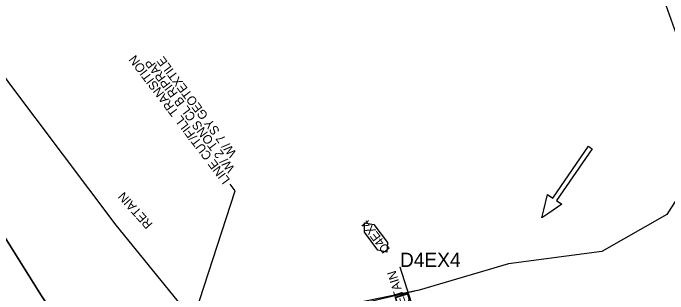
# Model space of a CAD drawing. Extents: x 465700 to 483515, y 488970 to 507540.
# Drawn here: x 476301 to 476667, y 501004.5 to 501161.6 of the extents above; entities that cross this region are included whole.
import ezdxf

# ---------------------------------------------------------------- set-up
doc = ezdxf.new("R2010")
doc.units = 0
for name, color, linetype in [('Default', 7, 'Continuous'), ('Exist Plan Preparation Drainage Flow Arrows', 7, 'Continuous'), ('Exist Plan Preparation Watershed Blue', 7, 'Continuous'), ('Prop Drainage Structure Box Number Symbol CELL', 7, 'Continuous'), ('Prop Drainage Structure Pipe Collar Label', 7, 'Continuous'), ('Prop Drainage Structure Pipe Stub Out CELL', 7, 'Continuous'), ('Prop Erosion Rip Rap Pad at Outlet Label', 7, 'Continuous'), ('Scratch_Level_8', 7, 'Continuous')]:
    doc.layers.add(name, color=color, linetype=linetype)

# ---------------------------------------------------------------- blocks, each defined once
blk = doc.blocks.new('Existing ground flow arrow')
at = {"layer": 'Default'}
blk.add_line((2.5, -4.33), (2.5, -4.33), dxfattribs=at)
blk.add_lwpolyline([(-1.29, -47.2), (-1.28, -12.53), (-4.77, -12.53), (-1.65, -4.33), (0, 0), (1.65, -4.33), (4.78, -12.53), (1.28, -12.52), (1.29, -47.19), (0, -47.2)], close=True, dxfattribs=at)

msp = doc.modelspace()

# ---------------------------------------------------------------- linework, layer by layer
at = {"layer": 'Exist Plan Preparation Watershed Blue'}
for points in [[(476921.2, 501693.96), (476873.97, 501665.49), (476797.54, 501630.58), (476778.04, 501586.57), (476684.08, 501524.02), (476617.13, 501430.2), (476608.09, 501344.67), (476632.2, 501297.34), (476652.85, 501202.84), (476684.48, 501113.94), (476686.07, 501079.86), (476666.3, 501048.93), (476630.01, 501028.21), (476577.87, 501021.26), (476528.03, 501006.59), (476466.6, 500992.22), (476420.26, 500966.99), (476486.96, 500889.51), (476555.03, 500816.27), (476625.62, 500745.44), (476698.65, 500677.13), (476726.48, 500652.21), (476834.31, 500555.52), (476965.29, 500641)], [(476922.43, 500477.32), (476847.82, 500543.91), (476773.22, 500610.51), (476698.65, 500677.13), (476625.62, 500745.44), (476555.03, 500816.27), (476486.96, 500889.51), (476420.26, 500966.99), (476358.7, 501042.92), (476298.67, 501122.89), (476241.47, 501204.91)], [(476965.29, 500641), (476834.31, 500555.52), (476726.48, 500652.21), (476625.62, 500745.44), (476555.03, 500816.27), (476486.96, 500889.51), (476420.26, 500966.99), (476358.7, 501042.92), (476298.67, 501122.89), (476241.47, 501204.91)], [(476652.85, 501202.84), (476684.48, 501113.94), (476686.07, 501079.86), (476666.3, 501048.93), (476630.01, 501028.21), (476577.87, 501021.26), (476528.03, 501006.59), (476497.08, 501000.21), (476482.89, 500996.49), (476466.6, 500992.22), (476455.71, 500986.82), (476443.7, 500979.93), (476439.14, 500977.28), (476420.26, 500966.99), (476358.7, 501042.92), (476298.67, 501122.89), (476241.47, 501204.91)], [(476209, 500683.6), (476345.39, 500652.36), (476467.07, 500616.53), (476565.07, 500627.06), (476600.68, 500664.31), (476574.27, 500687.93), (476537.67, 500723.12), (476510.19, 500751.77), (476483.11, 500782.17), (476453.04, 500818.7), (476434.2, 500842.61), (476385.69, 500904.17), (476387.26, 500905.41), (476372.86, 500924.02), (476358.8, 500942.89), (476340.03, 500969.19), (476316.98, 501003.43), (476294.62, 501039.29)], [(476294.62, 501039.29), (476316.98, 501003.43), (476340.03, 500969.19), (476358.8, 500942.89), (476372.86, 500924.02), (476387.26, 500905.42), (476401.7, 500887.09), (476416.14, 500868.76), (476414.56, 500867.51), (476424.17, 500855.35), (476438.61, 500837.03), (476453.04, 500818.7), (476467.88, 500800.28), (476483.11, 500782.17), (476510.19, 500751.77), (476537.67, 500723.12), (476574.27, 500687.93)]]:
    msp.add_lwpolyline(points, dxfattribs=at)
at = {"layer": 'Prop Drainage Structure Box Number Symbol CELL'}
msp.add_lwpolyline([(476504.93, 501029.08), (476497.32, 501039.13), (476497.42, 501044.35), (476502.66, 501043.37), (476510.27, 501033.32), (476509.83, 501027.97), (476504.93, 501029.08)], dxfattribs=at)
at = {"layer": 'Prop Drainage Structure Pipe Stub Out CELL'}
msp.add_line((476517.23, 501019.61), (476517.23, 501019.61), dxfattribs=at)
msp.add_line((476517.23, 501019.61), (476517.23, 501019.61), dxfattribs=at)
msp.add_lwpolyline([(476517.22, 501019.62), (476517.24, 501019.61), (476517.23, 501019.59), (476517.21, 501019.6), (476517.22, 501019.62)], dxfattribs=at)
at = {"layer": 'Prop Erosion Rip Rap Pad at Outlet Label'}
msp.add_lwpolyline([(476390.32, 500954.98), (476425.16, 501062.12), (476422.28, 501065.93)], dxfattribs=at)
at = {"layer": 'Scratch_Level_8'}
msp.add_line((476517.23, 501019.61), (476525.77, 500992.62), dxfattribs=at)

# ---------------------------------------------------------------- block references
at = {"layer": 'Exist Plan Preparation Drainage Flow Arrows', "xscale": 1.012407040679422, "yscale": 1.0124070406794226, "rotation": 145.49469097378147}
msp.add_blockref('Existing ground flow arrow', (476596.51, 501047), dxfattribs=at)

# ---------------------------------------------------------------- texts
at = {"layer": 'Prop Drainage Structure Box Number Symbol CELL'}
msp.add_text('D4EX4', height=5, rotation=127.1208, dxfattribs=at).set_placement((476511.92, 501029.61))
at = {"layer": 'Prop Drainage Structure Pipe Collar Label'}
for rotation, p in [(131.746, (476379.32, 501043.7)), (107.5926, (476522.15, 500994.59))]:
    msp.add_text('RETAIN', height=5, rotation=rotation, dxfattribs=at).set_placement(p)
at = {"layer": 'Prop Drainage Structure Pipe Stub Out CELL'}
msp.add_text('SO', height=0.0104, rotation=277.6891, dxfattribs=at).set_placement((476517.22, 501019.61))
at = {"layer": 'Prop Erosion Rip Rap Pad at Outlet Label'}
for s, p in [('LINE CUT/FILL TRANSITION ', (476422.48, 501068.37)), ('W/ 2 TONS CL B RIPRAP', (476425.18, 501074.74)), ('W/ 7 SY GEOTEXTILE', (476426.22, 501083.32))]:
    msp.add_text(s, height=5, rotation=127.1092, dxfattribs=at).set_placement(p)
at = {"layer": 'Scratch_Level_8'}
msp.add_text('D4EX4', height=8, dxfattribs=at).set_placement((476517.23, 501019.61))
msp.add_text('D4EX4', height=8, rotation=287.5659, dxfattribs=at).set_placement((476513.87, 501003.7))

doc.saveas('drawing.dxf')
